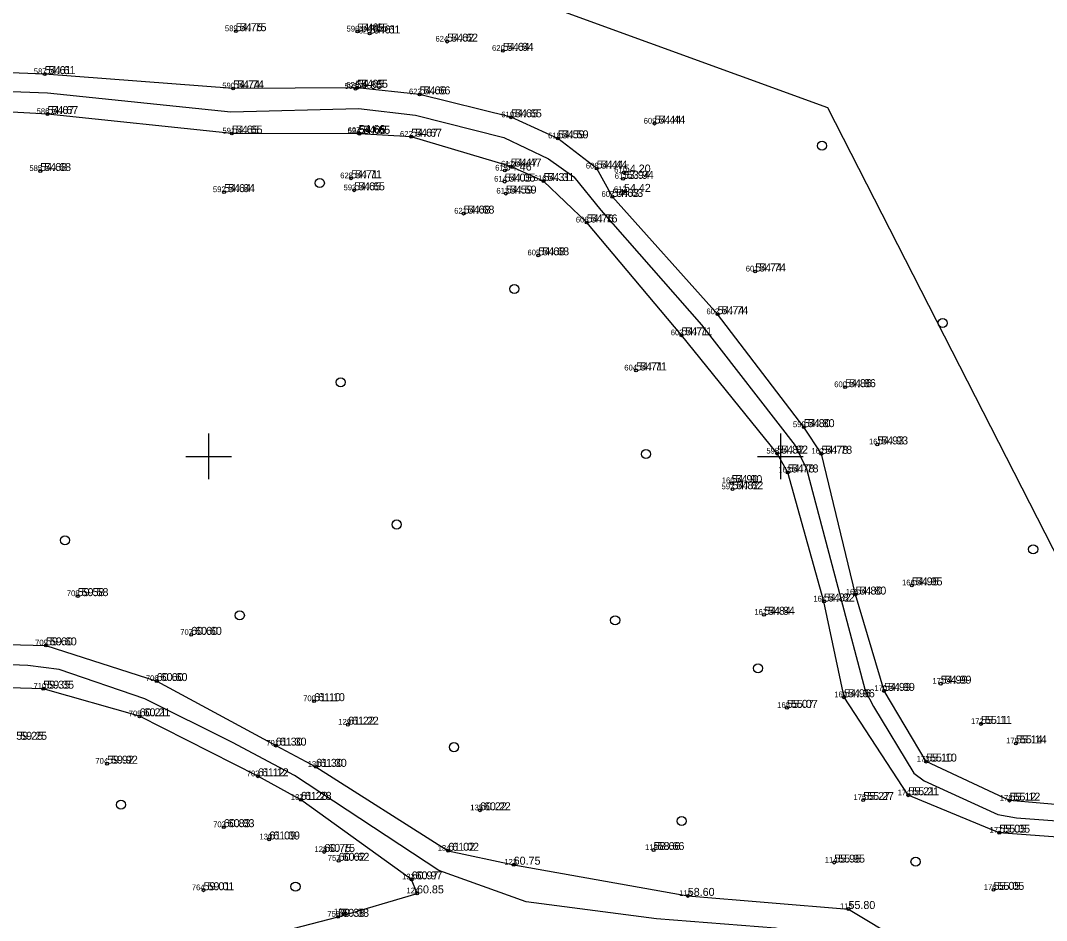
# Model space of a CAD drawing. Extents: x 554846 to 556995, y 6445875 to 6446723.
# Drawn here: x 555383.6 to 555473.3, y 6446209.4 to 6446288.1 of the extents above; entities that cross this region are included whole.
import ezdxf

# ---------------------------------------------------------------- set-up
doc = ezdxf.new("R2010")
doc.units = 0
for name, color, linetype in [('HALJASTUS', 7, 'Continuous'), ('KORGUS-EH2000', 7, 'Continuous'), ('MOOTKORG-EH2000', 7, 'Continuous'), ('MOOTMPUNKT', 7, 'Continuous'), ('MOOTNR', 7, 'Continuous'), ('MOOTPIIR', 7, 'Continuous'), ('TEE', 7, 'Continuous'), ('VORK', 7, 'Continuous')]:
    doc.layers.add(name, color=color, linetype=linetype)

msp = doc.modelspace()

# ---------------------------------------------------------------- linework, layer by layer
at = {"layer": 'HALJASTUS'}
for centre in [(555453.641, 6446277.161), (555409.721, 6446273.896), (555426.729, 6446264.634), (555464.189, 6446261.658), (555411.551, 6446256.475), (555438.246, 6446250.202), (555416.449, 6446244.036), (555387.44, 6446242.662), (555472.101, 6446241.868), (555402.725, 6446236.093), (555435.555, 6446235.662), (555448.042, 6446231.462), (555421.454, 6446224.569), (555392.338, 6446219.534), (555441.368, 6446218.107), (555461.82, 6446214.552), (555407.596, 6446212.371)]:
    msp.add_circle(centre, 0.4, dxfattribs=at)
at = {"layer": 'KORGUS-EH2000'}
for centre in [(555402.375, 6446287.18), (555413.013, 6446287.15), (555414.078, 6446286.979), (555420.861, 6446286.267), (555425.733, 6446285.46), (555385.664, 6446283.423), (555402.146, 6446282.172), (555412.991, 6446282.233), (555418.45, 6446281.655), (555385.908, 6446279.935), (555426.445, 6446279.648), (555438.995, 6446279.098), (555402.031, 6446278.228), (555413.19, 6446278.206), (555417.712, 6446277.949), (555430.534, 6446277.805), (555385.277, 6446274.952), (555426.418, 6446275.341), (555433.937, 6446275.167), (555412.457, 6446274.315), (555425.889, 6446274.024), (555429.285, 6446274.072), (555436.235, 6446274.266), (555401.352, 6446273.102), (555412.726, 6446273.266), (555425.989, 6446272.977), (555435.307, 6446272.69), (555422.3, 6446271.228), (555433.063, 6446270.451), (555428.832, 6446267.576), (555447.795, 6446266.166), (555444.507, 6446262.428), (555441.339, 6446260.584), (555437.376, 6446257.508), (555455.654, 6446256.048), (555452.046, 6446252.552), (555458.469, 6446251.042), (555449.723, 6446250.241), (555453.585, 6446250.221), (555450.64, 6446248.59), (555445.724, 6446247.657), (555445.807, 6446247.123), (555461.488, 6446238.714), (555388.55, 6446237.774), (555453.807, 6446237.305), (555456.566, 6446237.911), (555448.569, 6446236.145), (555398.469, 6446234.387), (555385.778, 6446233.467), (555395.46, 6446230.347), (555464.015, 6446230.117), (555385.539, 6446229.679), (555459.066, 6446229.486), (555409.219, 6446228.587), (555455.562, 6446228.932), (555450.571, 6446228.005), (555393.965, 6446227.264), (555412.186, 6446226.535), (555467.539, 6446226.599), (555405.87, 6446224.702), (555470.591, 6446224.897), (555391.121, 6446223.12), (555409.386, 6446222.845), (555462.737, 6446223.304), (555404.309, 6446222.02), (555461.182, 6446220.358), (555408.066, 6446219.96), (555457.238, 6446219.945), (555470.035, 6446219.891), (555423.728, 6446219.046), (555401.32, 6446217.571), (555469.141, 6446217.085), (555405.298, 6446216.494), (555410.11, 6446215.404), (555420.953, 6446215.507), (555438.912, 6446215.572), (555411.369, 6446214.628), (555454.707, 6446214.472), (555417.749, 6446213.004), (555399.555, 6446212.055), (555468.635, 6446212.085), (555411.335, 6446209.731)]:
    msp.add_circle(centre, 0.125, dxfattribs=at)
at = {"layer": 'MOOTMPUNKT'}
for centre in [(555402.375, 6446287.18), (555413.013, 6446287.15), (555414.078, 6446286.979), (555420.861, 6446286.267), (555425.733, 6446285.46), (555385.664, 6446283.423), (555402.146, 6446282.172), (555412.841, 6446282.138), (555412.991, 6446282.233), (555418.45, 6446281.655), (555385.908, 6446279.935), (555426.445, 6446279.648), (555438.995, 6446279.098), (555402.031, 6446278.228), (555413.107, 6446278.274), (555413.19, 6446278.206), (555417.712, 6446277.949), (555430.534, 6446277.805), (555385.277, 6446274.952), (555425.907, 6446274.991), (555426.418, 6446275.341), (555433.937, 6446275.167), (555412.457, 6446274.315), (555425.889, 6446274.024), (555429.285, 6446274.072), (555436.235, 6446274.266), (555436.311, 6446274.815), (555401.352, 6446273.102), (555412.726, 6446273.266), (555436.322, 6446273.124), (555425.989, 6446272.977), (555435.307, 6446272.69), (555422.3, 6446271.228), (555433.063, 6446270.451), (555428.832, 6446267.576), (555447.795, 6446266.166), (555444.507, 6446262.428), (555441.339, 6446260.584), (555437.376, 6446257.508), (555455.654, 6446256.048), (555452.046, 6446252.552), (555458.469, 6446251.042), (555449.723, 6446250.241), (555453.585, 6446250.221), (555450.64, 6446248.59), (555445.724, 6446247.657), (555445.807, 6446247.123), (555461.488, 6446238.714), (555388.55, 6446237.774), (555453.807, 6446237.305), (555456.566, 6446237.911), (555448.569, 6446236.145), (555398.469, 6446234.387), (555385.778, 6446233.467), (555395.46, 6446230.347), (555464.015, 6446230.117), (555385.539, 6446229.679), (555459.066, 6446229.486), (555409.219, 6446228.587), (555455.562, 6446228.932), (555450.571, 6446228.005), (555393.965, 6446227.264), (555412.186, 6446226.535), (555467.539, 6446226.599), (555405.87, 6446224.702), (555470.591, 6446224.897), (555391.121, 6446223.12), (555409.386, 6446222.845), (555462.737, 6446223.304), (555404.309, 6446222.02), (555461.182, 6446220.358), (555408.066, 6446219.96), (555457.238, 6446219.945), (555470.035, 6446219.891), (555423.728, 6446219.046), (555401.32, 6446217.571), (555469.141, 6446217.085), (555405.298, 6446216.494), (555410.11, 6446215.404), (555420.953, 6446215.507), (555438.912, 6446215.572), (555411.369, 6446214.628), (555426.678, 6446214.289), (555454.707, 6446214.472), (555417.749, 6446213.004), (555399.555, 6446212.055), (555468.635, 6446212.085), (555418.226, 6446211.78), (555441.901, 6446211.558), (555455.955, 6446210.414), (555411.335, 6446209.731), (555411.823, 6446209.957)]:
    msp.add_circle(centre, 0.125, dxfattribs=at)
at = {"layer": 'MOOTPIIR'}
msp.add_lwpolyline([(555188.077, 6446295.667), (555274.445, 6446293.028), (555305.103, 6446287.75), (555351.913, 6446294.017), (555415.206, 6446294.677), (555454.104, 6446280.494), (555476.52, 6446236.626), (555494.981, 6446232.668), (555576.074, 6446239.924), (555660.794, 6446267.96), (555725.406, 6446281.484), (555817.048, 6446350.749)], dxfattribs=at)
at = {"layer": 'TEE'}
for points in [[(555480.055, 6446219.037), (555470.035, 6446219.891), (555462.737, 6446223.304), (555459.066, 6446229.486), (555456.566, 6446237.911), (555453.585, 6446250.221), (555452.046, 6446252.552), (555444.507, 6446262.428), (555435.307, 6446272.69), (555433.937, 6446275.167), (555430.534, 6446277.805), (555426.445, 6446279.648), (555418.45, 6446281.655), (555412.991, 6446282.233), (555402.146, 6446282.172), (555385.664, 6446283.423), (555376.7, 6446283.776)], [(555376.586, 6446282.139), (555385.915, 6446281.774), (555401.933, 6446280.135), (555413.097, 6446280.404), (555418.1, 6446279.846), (555425.829, 6446277.884), (555429.715, 6446276.022), (555431.927, 6446274.429), (555434.284, 6446271.534), (555443.099, 6446261.499), (555451.297, 6446250.954), (555452.287, 6446248.917), (555455.287, 6446237.58), (555457.416, 6446229.532), (555458.141, 6446228.128), (555461.678, 6446222.285), (555462.564, 6446221.623), (555469.021, 6446218.674), (555470.651, 6446218.378), (555479.672, 6446217.723)], [(555479.328, 6446216.321), (555469.141, 6446217.085), (555461.182, 6446220.358), (555455.562, 6446228.932), (555453.807, 6446237.305), (555450.64, 6446248.59), (555449.723, 6446250.241), (555441.339, 6446260.584), (555433.063, 6446270.451), (555429.285, 6446274.072), (555426.418, 6446275.341), (555417.712, 6446277.949), (555413.19, 6446278.206), (555402.031, 6446278.228), (555385.908, 6446279.935), (555376.593, 6446280.453)], [(555377.982, 6446233.661), (555385.778, 6446233.467), (555395.46, 6446230.347), (555405.87, 6446224.702), (555409.386, 6446222.845), (555420.953, 6446215.507), (555426.678, 6446214.289), (555441.901, 6446211.558), (555455.955, 6446210.414), (555469.637, 6446202.173), (555476.682, 6446197.344)], [(555475.136, 6446196.652), (555461.497, 6446204.471), (555455.311, 6446207.569), (555449.584, 6446208.728), (555439.165, 6446209.561), (555427.759, 6446211.043), (555420.126, 6446213.794), (555407.523, 6446222.088), (555402.096, 6446224.984), (555394.437, 6446228.805), (555386.933, 6446231.369), (555384.183, 6446231.72), (555378.357, 6446231.933)], [(555417.749, 6446213.004), (555408.066, 6446219.96), (555404.309, 6446222.02), (555393.965, 6446227.264), (555385.539, 6446229.679), (555377.588, 6446229.894)], [(555375.151, 6446199.451), (555387.148, 6446203.23), (555400.189, 6446206.83), (555411.335, 6446209.731), (555418.226, 6446211.78), (555417.749, 6446213.004)]]:
    msp.add_lwpolyline(points, dxfattribs=at)
at = {"layer": 'VORK'}
for p, q in [((555400, 6446252), (555400, 6446248)), ((555450, 6446252), (555450, 6446248)), ((555398, 6446250), (555402, 6446250)), ((555448, 6446250), (555452, 6446250))]:
    msp.add_line(p, q, dxfattribs=at)

# ---------------------------------------------------------------- texts
at = {"layer": 'KORGUS-EH2000'}
for s, p in [('54.75', (555402.725, 6446287.18)), ('54.65', (555413.363, 6446287.15)), ('54.61', (555414.428, 6446286.979)), ('54.62', (555421.211, 6446286.267)), ('54.64', (555426.083, 6446285.46)), ('54.61', (555386.014, 6446283.423)), ('54.74', (555402.496, 6446282.172)), ('54.65', (555413.341, 6446282.233)), ('54.66', (555418.8, 6446281.655)), ('54.67', (555386.258, 6446279.935)), ('54.65', (555426.795, 6446279.648)), ('54.44', (555439.345, 6446279.098)), ('54.65', (555402.381, 6446278.228)), ('54.65', (555413.54, 6446278.206)), ('54.67', (555418.062, 6446277.949)), ('54.59', (555430.884, 6446277.805)), ('54.47', (555426.768, 6446275.341)), ('54.44', (555434.287, 6446275.167)), ('54.68', (555385.627, 6446274.952)), ('54.71', (555412.807, 6446274.315)), ('53.94', (555436.585, 6446274.266)), ('54.05', (555426.239, 6446274.024)), ('54.31', (555429.635, 6446274.072)), ('54.64', (555401.702, 6446273.102)), ('54.65', (555413.076, 6446273.266)), ('54.59', (555426.339, 6446272.977)), ('54.63', (555435.657, 6446272.69)), ('54.68', (555422.65, 6446271.228)), ('54.76', (555433.413, 6446270.451)), ('54.68', (555429.182, 6446267.576)), ('54.74', (555448.145, 6446266.166)), ('54.74', (555444.857, 6446262.428)), ('54.71', (555441.689, 6446260.584)), ('54.71', (555437.726, 6446257.508)), ('54.86', (555456.004, 6446256.048)), ('54.80', (555452.396, 6446252.552)), ('54.93', (555458.819, 6446251.042)), ('54.82', (555450.073, 6446250.241)), ('54.78', (555453.935, 6446250.221)), ('54.78', (555450.99, 6446248.59)), ('54.90', (555446.074, 6446247.657)), ('54.82', (555446.157, 6446247.123)), ('54.95', (555461.838, 6446238.714)), ('59.58', (555388.9, 6446237.774)), ('54.80', (555456.916, 6446237.911)), ('54.82', (555454.157, 6446237.305)), ('54.84', (555448.919, 6446236.145)), ('60.60', (555398.819, 6446234.387)), ('59.60', (555386.128, 6446233.467)), ('60.60', (555395.81, 6446230.347)), ('59.35', (555385.889, 6446229.679)), ('54.99', (555459.416, 6446229.486)), ('54.99', (555464.365, 6446230.117)), ('61.10', (555409.569, 6446228.587)), ('54.96', (555455.912, 6446228.932)), ('55.07', (555450.921, 6446228.005)), ('60.21', (555394.315, 6446227.264)), ('61.22', (555412.536, 6446226.535)), ('55.11', (555467.889, 6446226.599)), ('59.25', (555383.527, 6446225.212)), ('61.30', (555406.22, 6446224.702)), ('55.14', (555470.941, 6446224.897)), ('59.92', (555391.471, 6446223.12)), ('55.10', (555463.087, 6446223.304)), ('61.30', (555409.736, 6446222.845)), ('61.12', (555404.659, 6446222.02)), ('61.28', (555408.416, 6446219.96)), ('55.27', (555457.588, 6446219.945)), ('55.21', (555461.532, 6446220.358)), ('55.12', (555470.385, 6446219.891)), ('60.22', (555424.078, 6446219.046)), ('60.83', (555401.67, 6446217.571)), ('55.05', (555469.491, 6446217.085)), ('61.09', (555405.648, 6446216.494)), ('60.75', (555410.46, 6446215.404)), ('61.02', (555421.303, 6446215.507)), ('58.66', (555439.262, 6446215.572)), ('60.62', (555411.719, 6446214.628)), ('55.95', (555455.057, 6446214.472)), ('60.97', (555418.099, 6446213.004)), ('59.01', (555399.905, 6446212.055)), ('55.05', (555468.985, 6446212.085)), ('60.38', (555411.685, 6446209.731))]:
    msp.add_text(s, height=0.7, dxfattribs=at).set_placement(p)
at = {"layer": 'MOOTKORG-EH2000'}
for s, p in [('54.75', (555402.375, 6446287.18)), ('54.65', (555413.013, 6446287.15)), ('54.61', (555414.078, 6446286.979)), ('54.62', (555420.861, 6446286.267)), ('54.64', (555425.733, 6446285.46)), ('54.61', (555385.664, 6446283.423)), ('54.74', (555402.146, 6446282.172)), ('54.65', (555412.841, 6446282.138)), ('54.65', (555412.991, 6446282.233)), ('54.66', (555418.45, 6446281.655)), ('54.67', (555385.908, 6446279.935)), ('54.65', (555426.445, 6446279.648)), ('54.44', (555438.995, 6446279.098)), ('54.65', (555402.031, 6446278.228)), ('54.66', (555413.107, 6446278.274)), ('54.65', (555413.19, 6446278.206)), ('54.67', (555417.712, 6446277.949)), ('54.59', (555430.534, 6446277.805)), ('54.47', (555426.418, 6446275.341)), ('54.44', (555433.937, 6446275.167)), ('54.68', (555385.277, 6446274.952)), ('54.71', (555412.457, 6446274.315)), ('54.46', (555425.907, 6446274.991)), ('53.94', (555436.235, 6446274.266)), ('54.20', (555436.311, 6446274.815)), ('54.05', (555425.889, 6446274.024)), ('54.31', (555429.285, 6446274.072)), ('54.64', (555401.352, 6446273.102)), ('54.65', (555412.726, 6446273.266)), ('54.59', (555425.989, 6446272.977)), ('54.63', (555435.307, 6446272.69)), ('54.42', (555436.322, 6446273.124)), ('54.68', (555422.3, 6446271.228)), ('54.76', (555433.063, 6446270.451)), ('54.68', (555428.832, 6446267.576)), ('54.74', (555447.795, 6446266.166)), ('54.74', (555444.507, 6446262.428)), ('54.71', (555441.339, 6446260.584)), ('54.71', (555437.376, 6446257.508)), ('54.86', (555455.654, 6446256.048)), ('54.80', (555452.046, 6446252.552)), ('54.93', (555458.469, 6446251.042)), ('54.82', (555449.723, 6446250.241)), ('54.78', (555453.585, 6446250.221)), ('54.78', (555450.64, 6446248.59)), ('54.90', (555445.724, 6446247.657)), ('54.82', (555445.807, 6446247.123)), ('54.95', (555461.488, 6446238.714)), ('59.58', (555388.55, 6446237.774)), ('54.80', (555456.566, 6446237.911)), ('54.82', (555453.807, 6446237.305)), ('54.84', (555448.569, 6446236.145)), ('60.60', (555398.469, 6446234.387)), ('59.60', (555385.778, 6446233.467)), ('60.60', (555395.46, 6446230.347)), ('59.35', (555385.539, 6446229.679)), ('54.99', (555459.066, 6446229.486)), ('54.99', (555464.015, 6446230.117)), ('61.10', (555409.219, 6446228.587)), ('54.96', (555455.562, 6446228.932)), ('55.07', (555450.571, 6446228.005)), ('60.21', (555393.965, 6446227.264)), ('61.22', (555412.186, 6446226.535)), ('55.11', (555467.539, 6446226.599)), ('59.25', (555383.177, 6446225.212)), ('61.30', (555405.87, 6446224.702)), ('55.14', (555470.591, 6446224.897)), ('59.92', (555391.121, 6446223.12)), ('55.10', (555462.737, 6446223.304)), ('61.30', (555409.386, 6446222.845)), ('61.12', (555404.309, 6446222.02)), ('61.28', (555408.066, 6446219.96)), ('55.27', (555457.238, 6446219.945)), ('55.21', (555461.182, 6446220.358)), ('55.12', (555470.035, 6446219.891)), ('60.22', (555423.728, 6446219.046)), ('60.83', (555401.32, 6446217.571)), ('55.05', (555469.141, 6446217.085)), ('61.09', (555405.298, 6446216.494)), ('60.75', (555410.11, 6446215.404)), ('61.02', (555420.953, 6446215.507)), ('58.66', (555438.912, 6446215.572)), ('60.62', (555411.369, 6446214.628)), ('60.75', (555426.678, 6446214.289)), ('55.95', (555454.707, 6446214.472)), ('60.97', (555417.749, 6446213.004)), ('59.01', (555399.555, 6446212.055)), ('60.85', (555418.226, 6446211.78)), ('58.60', (555441.901, 6446211.558)), ('55.05', (555468.635, 6446212.085)), ('60.38', (555411.335, 6446209.731)), ('55.80', (555455.955, 6446210.414))]:
    msp.add_text(s, height=0.7, dxfattribs=at).set_placement(p)
at = {"layer": 'MOOTNR'}
for s, p in [('589', (555401.425, 6446287.18)), ('596', (555412.063, 6446287.15)), ('625', (555413.128, 6446286.979)), ('624', (555419.836, 6446286.267)), ('620', (555424.783, 6446285.46)), ('587', (555384.714, 6446283.423)), ('590', (555401.196, 6446282.172)), ('595', (555411.891, 6446282.138)), ('626', (555412.041, 6446282.233)), ('623', (555417.525, 6446281.655)), ('586', (555384.958, 6446279.935)), ('619', (555425.595, 6446279.648)), ('609', (555438.045, 6446279.098)), ('591', (555401.206, 6446278.228)), ('627', (555412.157, 6446278.274)), ('594', (555412.165, 6446278.206)), ('622', (555416.737, 6446277.949)), ('618', (555429.684, 6446277.805)), ('585', (555384.327, 6446274.952)), ('615', (555425.057, 6446274.991)), ('617', (555425.568, 6446275.341)), ('608', (555432.987, 6446275.167)), ('610', (555435.461, 6446274.815)), ('628', (555411.507, 6446274.315)), ('614', (555424.964, 6446274.024)), ('616', (555428.435, 6446274.072)), ('611', (555435.51, 6446274.266)), ('592', (555400.377, 6446273.102)), ('593', (555411.801, 6446273.266)), ('613', (555425.164, 6446272.977)), ('607', (555434.357, 6446272.69)), ('612', (555435.447, 6446273.124)), ('621', (555421.475, 6446271.228)), ('606', (555432.113, 6446270.451)), ('605', (555427.882, 6446267.576)), ('601', (555446.97, 6446266.166)), ('602', (555443.532, 6446262.428)), ('603', (555440.414, 6446260.584)), ('604', (555436.351, 6446257.508)), ('600', (555454.704, 6446256.048)), ('599', (555451.096, 6446252.552)), ('598', (555448.773, 6446250.241)), ('161', (555457.744, 6446251.042)), ('162', (555452.71, 6446250.221)), ('163', (555449.815, 6446248.59)), ('160', (555444.874, 6446247.657)), ('597', (555444.857, 6446247.123)), ('166', (555460.638, 6446238.714)), ('708', (555387.6, 6446237.774)), ('165', (555455.716, 6446237.911)), ('164', (555452.882, 6446237.305)), ('167', (555447.719, 6446236.145)), ('707', (555397.519, 6446234.387)), ('709', (555384.828, 6446233.467)), ('710', (555384.689, 6446229.679)), ('706', (555394.51, 6446230.347)), ('171', (555463.29, 6446230.117)), ('169', (555454.712, 6446228.932)), ('170', (555458.216, 6446229.486)), ('700', (555408.269, 6446228.587)), ('168', (555449.721, 6446228.005)), ('705', (555393.015, 6446227.264)), ('129', (555411.336, 6446226.535)), ('172', (555466.664, 6446226.599)), ('701', (555405.045, 6446224.702)), ('179', (555469.741, 6446224.897)), ('704', (555390.096, 6446223.12)), ('131', (555408.661, 6446222.845)), ('173', (555461.912, 6446223.304)), ('702', (555403.334, 6446222.02)), ('132', (555407.191, 6446219.96)), ('175', (555456.388, 6446219.945)), ('174', (555460.257, 6446220.358)), ('178', (555469.185, 6446219.891)), ('135', (555422.878, 6446219.046)), ('703', (555400.395, 6446217.571)), ('177', (555468.291, 6446217.085)), ('130', (555404.448, 6446216.494)), ('128', (555409.26, 6446215.404)), ('134', (555420.028, 6446215.507)), ('119', (555438.162, 6446215.572)), ('757', (555410.419, 6446214.628)), ('114', (555453.882, 6446214.472)), ('123', (555425.853, 6446214.289)), ('133', (555416.924, 6446213.004)), ('764', (555398.53, 6446212.055)), ('124', (555417.301, 6446211.78)), ('176', (555467.785, 6446212.085)), ('118', (555441.151, 6446211.558)), ('125', (555410.973, 6446209.957)), ('20', (555411.551, 6446209.945)), ('115', (555455.205, 6446210.414)), ('758', (555410.385, 6446209.731))]:
    msp.add_text(s, height=0.5, dxfattribs=at).set_placement(p)

doc.saveas('drawing.dxf')
